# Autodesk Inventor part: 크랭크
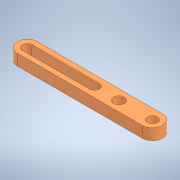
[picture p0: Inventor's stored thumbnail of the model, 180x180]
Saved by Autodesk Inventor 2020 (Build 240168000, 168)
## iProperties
Created: 2024-04
Part Number: 크랭크
Material: 알루미늄 6061
Document SubType Name: Modeling
Designer: oem
Density: 2.71 g/cm^3
Appearance: 기본값
Author: jhkim
Sending System: Autodesk Inventor 2025
Preprocessor: ST-DEVELOPER v20
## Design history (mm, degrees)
feature "솔리드1"
node "솔리드2"
